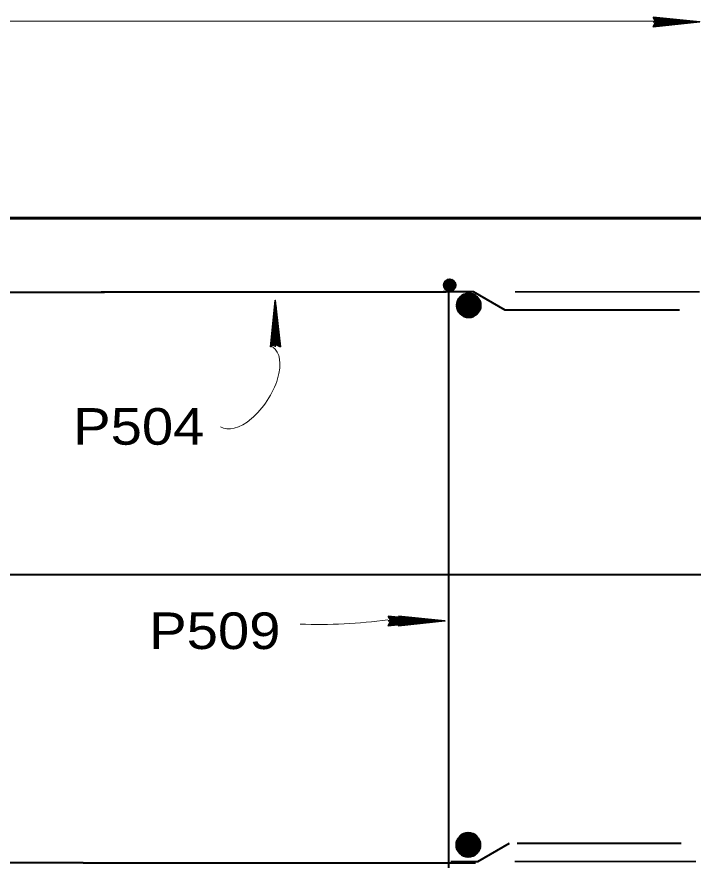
# Model space of a CAD drawing. Extents: x 3.64 to 6.84, y -0.8 to 1.19.
# Drawn here: x 4.3787 to 4.533, y 0.7206 to 0.9146 of the extents above; entities that cross this region are included whole.
import ezdxf

# ---------------------------------------------------------------- set-up
doc = ezdxf.new("R2010")
doc.units = 0
doc.header["$LTSCALE"] = 0.0033
doc.layers.add('1', color=7, linetype='Continuous', lineweight=40)

msp = doc.modelspace()

# ---------------------------------------------------------------- linework, layer by layer
at = {"layer": '1', "lineweight": 35}
for p, q in [((4.524, 0.9145), (4.531833, 0.913583)), ((4.524, 0.9145), (4.531833, 0.913583)), ((4.524, 0.914417), (4.531833, 0.913583)), ((4.524, 0.914333), (4.531833, 0.9135)), ((4.524, 0.914333), (4.531833, 0.913333)), ((4.52375, 0.9135), (4.534333, 0.9135)), ((4.523917, 0.912833), (4.53125, 0.913583)), ((4.524, 0.912667), (4.531333, 0.9135)), ((4.524, 0.912583), (4.531333, 0.913333)), ((4.524, 0.912417), (4.531333, 0.91325)), ((4.49225, 0.851917), (4.53425, 0.851917)), ((4.437583, 0.839417), (4.437583, 0.85)), ((4.437583, 0.839417), (4.437583, 0.85)), ((4.436583, 0.839667), (4.4375, 0.8475)), ((4.436583, 0.839667), (4.4375, 0.8475)), ((4.436583, 0.839667), (4.4375, 0.8475)), ((4.436583, 0.839667), (4.4375, 0.8475)), ((4.436667, 0.839667), (4.4375, 0.8475)), ((4.436667, 0.839667), (4.4375, 0.8475)), ((4.43675, 0.839667), (4.437583, 0.8475)), ((4.43675, 0.839667), (4.43775, 0.8475)), ((4.43675, 0.839667), (4.437583, 0.8475)), ((4.43675, 0.839667), (4.43775, 0.8475)), ((4.43825, 0.839583), (4.4375, 0.846917)), ((4.43825, 0.839583), (4.4375, 0.846917)), ((4.438417, 0.839667), (4.437583, 0.847)), ((4.438417, 0.839667), (4.437583, 0.847)), ((4.4385, 0.839667), (4.43775, 0.847)), ((4.4385, 0.839667), (4.43775, 0.847)), ((4.438667, 0.839667), (4.437833, 0.847)), ((4.438667, 0.839667), (4.437833, 0.847)), ((4.463333, 0.776917), (4.473917, 0.776917)), ((4.463333, 0.776917), (4.473917, 0.776917)), ((4.4635, 0.77625), (4.470833, 0.777)), ((4.4635, 0.77625), (4.470833, 0.777)), ((4.463583, 0.777917), (4.471417, 0.777)), ((4.463583, 0.777917), (4.471417, 0.777)), ((4.463583, 0.777917), (4.471417, 0.777)), ((4.463583, 0.777917), (4.471417, 0.777)), ((4.463583, 0.777833), (4.471417, 0.777)), ((4.463583, 0.777833), (4.471417, 0.777)), ((4.463583, 0.77775), (4.471417, 0.776917)), ((4.463583, 0.77775), (4.471417, 0.77675)), ((4.463583, 0.77775), (4.471417, 0.776917)), ((4.463583, 0.77775), (4.471417, 0.77675)), ((4.463583, 0.776083), (4.470917, 0.776917)), ((4.463583, 0.776083), (4.470917, 0.776917)), ((4.463583, 0.776), (4.470917, 0.77675)), ((4.463583, 0.776), (4.470917, 0.77675)), ((4.463583, 0.775833), (4.470917, 0.776667)), ((4.463583, 0.775833), (4.470917, 0.776667)), ((4.465667, 0.776917), (4.47625, 0.776917)), ((4.465667, 0.776917), (4.47625, 0.776917)), ((4.465833, 0.77625), (4.473167, 0.777)), ((4.465833, 0.77625), (4.473167, 0.777)), ((4.465917, 0.777917), (4.47375, 0.777)), ((4.465917, 0.777917), (4.47375, 0.777)), ((4.465917, 0.777917), (4.47375, 0.777)), ((4.465917, 0.777917), (4.47375, 0.777)), ((4.465917, 0.777833), (4.47375, 0.777)), ((4.465917, 0.777833), (4.47375, 0.777)), ((4.465917, 0.77775), (4.47375, 0.776917)), ((4.465917, 0.77775), (4.47375, 0.77675)), ((4.465917, 0.77775), (4.47375, 0.776917)), ((4.465917, 0.77775), (4.47375, 0.77675)), ((4.465917, 0.776083), (4.47325, 0.776917)), ((4.465917, 0.776083), (4.47325, 0.776917)), ((4.465917, 0.776), (4.47325, 0.77675)), ((4.465917, 0.776), (4.47325, 0.77675)), ((4.465917, 0.775833), (4.47325, 0.776667)), ((4.465917, 0.775833), (4.47325, 0.776667)), ((4.492167, 0.722083), (4.533417, 0.722083))]:
    msp.add_line(p, q, dxfattribs=at)
at = {"layer": '1', "lineweight": 13}
msp.add_line((4.117, 0.913667), (4.533, 0.913667), dxfattribs=at)
at = {"layer": '1', "lineweight": 60}
for p, q in [((4.157167, 0.86875), (4.492917, 0.86875)), ((4.399333, 0.86875), (4.53725, 0.86875)), ((4.479167, 0.84825), (4.479333, 0.850083)), ((4.479417, 0.850167), (4.479583, 0.84725)), ((4.479667, 0.850167), (4.479833, 0.84725)), ((4.479833, 0.850167), (4.480083, 0.84725)), ((4.48, 0.850167), (4.480167, 0.84725)), ((4.480167, 0.850167), (4.480417, 0.84725)), ((4.480417, 0.85025), (4.480583, 0.847333)), ((4.4805, 0.85025), (4.480667, 0.847333)), ((4.480667, 0.85025), (4.480833, 0.847333)), ((4.48075, 0.85025), (4.480917, 0.847333)), ((4.480917, 0.85025), (4.481167, 0.847333)), ((4.481167, 0.85025), (4.481417, 0.847333)), ((4.481417, 0.850333), (4.481583, 0.847417)), ((4.481583, 0.850333), (4.481833, 0.847417)), ((4.481833, 0.850333), (4.482, 0.847417)), ((4.482, 0.850333), (4.482167, 0.847417)), ((4.482167, 0.850333), (4.482333, 0.847417)), ((4.48225, 0.850417), (4.4825, 0.847417)), ((4.4825, 0.850417), (4.482667, 0.847417)), ((4.48275, 0.850417), (4.482917, 0.847417)), ((4.482917, 0.850417), (4.483167, 0.847417)), ((4.483083, 0.850417), (4.48325, 0.847417)), ((4.48325, 0.850417), (4.4835, 0.8475)), ((4.4835, 0.850417), (4.483667, 0.8475)), ((4.479167, 0.84825), (4.483917, 0.8475)), ((4.479083, 0.72525), (4.47925, 0.727083)), ((4.479333, 0.727167), (4.4795, 0.72425)), ((4.479583, 0.727167), (4.47975, 0.72425)), ((4.47975, 0.727167), (4.48, 0.72425)), ((4.479917, 0.727167), (4.480083, 0.72425)), ((4.480083, 0.727167), (4.480333, 0.72425)), ((4.480333, 0.72725), (4.4805, 0.724333)), ((4.480417, 0.72725), (4.480583, 0.724333)), ((4.480583, 0.72725), (4.48075, 0.724333)), ((4.480667, 0.72725), (4.480833, 0.724333)), ((4.480833, 0.72725), (4.481083, 0.724333)), ((4.481083, 0.72725), (4.481333, 0.724333)), ((4.481333, 0.727333), (4.4815, 0.724417)), ((4.4815, 0.727333), (4.48175, 0.724417)), ((4.48175, 0.727333), (4.481917, 0.724417)), ((4.481917, 0.727333), (4.482083, 0.724417)), ((4.482083, 0.727333), (4.48225, 0.724417)), ((4.482167, 0.727417), (4.482417, 0.724417)), ((4.482417, 0.727417), (4.482583, 0.724417)), ((4.482667, 0.727417), (4.482833, 0.724417)), ((4.482833, 0.727417), (4.483083, 0.724417)), ((4.483, 0.727417), (4.483167, 0.724417)), ((4.483167, 0.727417), (4.483417, 0.7245)), ((4.483417, 0.727417), (4.483583, 0.7245)), ((4.479083, 0.72525), (4.483833, 0.7245))]:
    msp.add_line(p, q, dxfattribs=at)
at = {"layer": '1'}
for p, q in [((4.476417, 0.85425), (4.476333, 0.85275)), ((4.476417, 0.85425), (4.476333, 0.85275)), ((4.476333, 0.85375), (4.478333, 0.853417)), ((4.476333, 0.85375), (4.478333, 0.853417)), ((4.476333, 0.853667), (4.478333, 0.85325)), ((4.476333, 0.853667), (4.478333, 0.85325)), ((4.4765, 0.85425), (4.476417, 0.85275)), ((4.476417, 0.85425), (4.478417, 0.853917)), ((4.4765, 0.85425), (4.476417, 0.85275)), ((4.476417, 0.85425), (4.478417, 0.853917)), ((4.476417, 0.854167), (4.478417, 0.853833)), ((4.476417, 0.854167), (4.478417, 0.853833)), ((4.476417, 0.854083), (4.478417, 0.853667)), ((4.476417, 0.854083), (4.478417, 0.853667)), ((4.476417, 0.854), (4.478417, 0.853583)), ((4.476417, 0.854), (4.478417, 0.853583)), ((4.476417, 0.853833), (4.478333, 0.8535)), ((4.476417, 0.853833), (4.478333, 0.8535)), ((4.4765, 0.854417), (4.478417, 0.854083)), ((4.4765, 0.854417), (4.478417, 0.854083)), ((4.476583, 0.85425), (4.4765, 0.85275)), ((4.476583, 0.85425), (4.4765, 0.85275)), ((4.476667, 0.85425), (4.476583, 0.85275)), ((4.476667, 0.85425), (4.476583, 0.85275)), ((4.47675, 0.85425), (4.476667, 0.85275)), ((4.47675, 0.85425), (4.476667, 0.85275)), ((4.476917, 0.85425), (4.476833, 0.85275)), ((4.476917, 0.85425), (4.476833, 0.85275)), ((4.477, 0.85425), (4.476917, 0.85275)), ((4.477, 0.85425), (4.476917, 0.85275)), ((4.477083, 0.85425), (4.477, 0.85275)), ((4.477083, 0.85425), (4.477, 0.85275)), ((4.477167, 0.85425), (4.477083, 0.85275)), ((4.477167, 0.85425), (4.477083, 0.85275)), ((4.47725, 0.85425), (4.477167, 0.85275)), ((4.47725, 0.85425), (4.477167, 0.85275)), ((4.477333, 0.85425), (4.47725, 0.85275)), ((4.477333, 0.85425), (4.47725, 0.85275)), ((4.477417, 0.85425), (4.477333, 0.85275)), ((4.477417, 0.85425), (4.477333, 0.85275)), ((4.477583, 0.854167), (4.477417, 0.852667)), ((4.477583, 0.854167), (4.477417, 0.852667)), ((4.47775, 0.854167), (4.477583, 0.852667)), ((4.47775, 0.854167), (4.477583, 0.852667)), ((4.477833, 0.854167), (4.47775, 0.852667)), ((4.477833, 0.854167), (4.47775, 0.852667)), ((4.477833, 0.854167), (4.47775, 0.852667)), ((4.477833, 0.854167), (4.47775, 0.852667)), ((4.477917, 0.854167), (4.477833, 0.852667)), ((4.477917, 0.854167), (4.477833, 0.852667)), ((4.478, 0.854167), (4.477917, 0.852667)), ((4.478, 0.854167), (4.477917, 0.852667)), ((4.478083, 0.854167), (4.478, 0.852667)), ((4.478083, 0.854167), (4.478, 0.852667)), ((4.478167, 0.854167), (4.478083, 0.852667)), ((4.478167, 0.854167), (4.478083, 0.852667)), ((4.47825, 0.854167), (4.478167, 0.852667)), ((4.47825, 0.854167), (4.478167, 0.852667)), ((4.478333, 0.854167), (4.47825, 0.852667)), ((4.478333, 0.854167), (4.47825, 0.852667)), ((4.4785, 0.854167), (4.478417, 0.852667)), ((4.4785, 0.854167), (4.478417, 0.852667)), ((4.397917, 0.851917), (4.4765, 0.851917)), ((4.476167, 0.852833), (4.478167, 0.8525)), ((4.476167, 0.852833), (4.478167, 0.8525)), ((4.47625, 0.853333), (4.47825, 0.852917)), ((4.47625, 0.853333), (4.47825, 0.852917)), ((4.47625, 0.853083), (4.47825, 0.85275)), ((4.47625, 0.853083), (4.47825, 0.85275)), ((4.47625, 0.853), (4.478167, 0.852667)), ((4.47625, 0.853), (4.478167, 0.852667)), ((4.47625, 0.852917), (4.478167, 0.852583)), ((4.47625, 0.852917), (4.478167, 0.852583)), ((4.476333, 0.853583), (4.47825, 0.853167)), ((4.476333, 0.853583), (4.47825, 0.853167)), ((4.476333, 0.8535), (4.47825, 0.853083)), ((4.476333, 0.8535), (4.47825, 0.853083)), ((4.477083, 0.851917), (4.477083, 0.720583)), ((4.477083, 0.851917), (4.477083, 0.720583)), ((4.48375, 0.850417), (4.479167, 0.84825)), ((4.479333, 0.850083), (4.480583, 0.85125)), ((4.483333, 0.85075), (4.4795, 0.850083)), ((4.483417, 0.850417), (4.4795, 0.84975)), ((4.483417, 0.85025), (4.4795, 0.8495)), ((4.4835, 0.85), (4.479583, 0.84925)), ((4.4835, 0.849833), (4.479583, 0.849083)), ((4.481417, 0.849917), (4.480083, 0.850917)), ((4.4835, 0.849583), (4.479667, 0.848833)), ((4.483583, 0.849417), (4.47975, 0.84875)), ((4.483583, 0.84925), (4.47975, 0.8485)), ((4.483667, 0.849), (4.479833, 0.84825)), ((4.483667, 0.848833), (4.479833, 0.848083)), ((4.48375, 0.848583), (4.479833, 0.847833)), ((4.483833, 0.848167), (4.479917, 0.847417)), ((4.483833, 0.848), (4.48, 0.84725)), ((4.479583, 0.84725), (4.483333, 0.846833)), ((4.483833, 0.84775), (4.48, 0.847083)), ((4.483917, 0.847667), (4.480083, 0.846917)), ((4.483917, 0.8475), (4.480083, 0.84675)), ((4.050917, 0.7875), (4.474833, 0.7875)), ((4.474833, 0.7875), (4.495917, 0.7875)), ((4.47925, 0.727083), (4.4805, 0.72825)), ((4.48325, 0.72775), (4.479417, 0.727083)), ((4.481333, 0.726917), (4.48, 0.727917)), ((4.483667, 0.727417), (4.479083, 0.72525)), ((4.483333, 0.727417), (4.479417, 0.72675)), ((4.483333, 0.72725), (4.479417, 0.7265)), ((4.483417, 0.727), (4.4795, 0.72625)), ((4.483417, 0.726833), (4.4795, 0.726083)), ((4.483417, 0.726583), (4.479583, 0.725833)), ((4.4835, 0.726417), (4.479667, 0.72575)), ((4.4835, 0.72625), (4.479667, 0.7255)), ((4.483583, 0.726), (4.47975, 0.72525)), ((4.483583, 0.725833), (4.47975, 0.725083)), ((4.483667, 0.725583), (4.47975, 0.724833)), ((4.530083, 0.726167), (4.49275, 0.726167)), ((4.4795, 0.72425), (4.48325, 0.723833)), ((4.48375, 0.725167), (4.479833, 0.724417)), ((4.48375, 0.725), (4.479917, 0.72425)), ((4.48375, 0.72475), (4.479917, 0.724083)), ((4.483833, 0.724667), (4.48, 0.723917)), ((4.483833, 0.7245), (4.48, 0.72375)), ((4.39375, 0.72175), (4.171167, 0.72175)), ((4.39375, 0.72175), (4.48325, 0.72175))]:
    msp.add_line(p, q, dxfattribs=at)
at = {"layer": '1', "lineweight": 35}
for points in [[(4.52375, 0.914583), (4.534333, 0.9135), (4.52375, 0.912333), (4.524333, 0.9135)], [(4.5245, 0.913583), (4.529167, 0.913667), (4.529167, 0.913583), (4.52825, 0.913583), (4.5245, 0.913667), (4.5275, 0.91375), (4.524333, 0.913833), (4.526583, 0.913917), (4.524333, 0.914), (4.527833, 0.91375), (4.5325, 0.913583), (4.531583, 0.913333), (4.532833, 0.913333), (4.5245, 0.913333), (4.526917, 0.913167), (4.524333, 0.913167), (4.529667, 0.913583), (4.524333, 0.912917)], [(4.4365, 0.839417), (4.437583, 0.85), (4.43875, 0.839417), (4.437583, 0.84)], [(4.4365, 0.839417), (4.437583, 0.85), (4.43875, 0.839417), (4.437583, 0.84)], [(4.4375, 0.840167), (4.437417, 0.844833), (4.4375, 0.844833), (4.4375, 0.843917), (4.437417, 0.840167), (4.437333, 0.843167), (4.43725, 0.84), (4.437167, 0.84225), (4.437083, 0.84), (4.437333, 0.8435), (4.4375, 0.848167), (4.43775, 0.84725), (4.43775, 0.8485), (4.43775, 0.840167), (4.437917, 0.842583), (4.437917, 0.84), (4.4375, 0.845333), (4.438167, 0.84)], [(4.4375, 0.840167), (4.437417, 0.844833), (4.4375, 0.844833), (4.4375, 0.843917), (4.437417, 0.840167), (4.437333, 0.843167), (4.43725, 0.84), (4.437167, 0.84225), (4.437083, 0.84), (4.437333, 0.8435), (4.4375, 0.848167), (4.43775, 0.84725), (4.43775, 0.8485), (4.43775, 0.840167), (4.437917, 0.842583), (4.437917, 0.84), (4.4375, 0.845333), (4.438167, 0.84)], [(4.463333, 0.778), (4.473917, 0.776917), (4.463333, 0.77575), (4.463917, 0.776917)], [(4.463333, 0.778), (4.473917, 0.776917), (4.463333, 0.77575), (4.463917, 0.776917)], [(4.465667, 0.778), (4.47625, 0.776917), (4.465667, 0.77575), (4.46625, 0.776917)], [(4.465667, 0.778), (4.47625, 0.776917), (4.465667, 0.77575), (4.46625, 0.776917)], [(4.464083, 0.777), (4.46875, 0.777083), (4.46875, 0.777), (4.467833, 0.777), (4.464083, 0.777083), (4.467083, 0.777167), (4.463917, 0.77725), (4.466167, 0.777333), (4.463917, 0.777417), (4.467417, 0.777167), (4.472083, 0.777), (4.471167, 0.77675), (4.472417, 0.77675), (4.464083, 0.77675), (4.4665, 0.776583), (4.463917, 0.776583), (4.46925, 0.777), (4.463917, 0.776333)], [(4.464083, 0.777), (4.46875, 0.777083), (4.46875, 0.777), (4.467833, 0.777), (4.464083, 0.777083), (4.467083, 0.777167), (4.463917, 0.77725), (4.466167, 0.777333), (4.463917, 0.777417), (4.467417, 0.777167), (4.472083, 0.777), (4.471167, 0.77675), (4.472417, 0.77675), (4.464083, 0.77675), (4.4665, 0.776583), (4.463917, 0.776583), (4.46925, 0.777), (4.463917, 0.776333)], [(4.466417, 0.777), (4.471083, 0.777083), (4.471083, 0.777), (4.470167, 0.777), (4.466417, 0.777083), (4.469417, 0.777167), (4.46625, 0.77725), (4.4685, 0.777333), (4.46625, 0.777417), (4.46975, 0.777167), (4.474417, 0.777), (4.4735, 0.77675), (4.47475, 0.77675), (4.466417, 0.77675), (4.468833, 0.776583), (4.46625, 0.776583), (4.471583, 0.777), (4.46625, 0.776333)], [(4.466417, 0.777), (4.471083, 0.777083), (4.471083, 0.777), (4.470167, 0.777), (4.466417, 0.777083), (4.469417, 0.777167), (4.46625, 0.77725), (4.4685, 0.777333), (4.46625, 0.777417), (4.46975, 0.777167), (4.474417, 0.777), (4.4735, 0.77675), (4.47475, 0.77675), (4.466417, 0.77675), (4.468833, 0.776583), (4.46625, 0.776583), (4.471583, 0.777), (4.46625, 0.776333)]]:
    msp.add_lwpolyline(points, close=True, dxfattribs=at)
for points in [[(4.5245, 0.913583), (4.524083, 0.914333), (4.524333, 0.914083), (4.5245, 0.91375), (4.52475, 0.913833), (4.524583, 0.914167), (4.524417, 0.913417), (4.52425, 0.912917), (4.524, 0.9125)], [(4.4375, 0.840167), (4.43675, 0.83975), (4.437, 0.84), (4.437333, 0.840167), (4.43725, 0.840417), (4.436917, 0.84025), (4.437667, 0.840083), (4.438167, 0.839917), (4.438583, 0.839667)], [(4.4375, 0.840167), (4.43675, 0.83975), (4.437, 0.84), (4.437333, 0.840167), (4.43725, 0.840417), (4.436917, 0.84025), (4.437667, 0.840083), (4.438167, 0.839917), (4.438583, 0.839667)], [(4.464083, 0.777), (4.463667, 0.77775), (4.463917, 0.7775), (4.464083, 0.777167), (4.464333, 0.77725), (4.464167, 0.777583), (4.464, 0.776833), (4.463833, 0.776333), (4.463583, 0.775917)], [(4.464083, 0.777), (4.463667, 0.77775), (4.463917, 0.7775), (4.464083, 0.777167), (4.464333, 0.77725), (4.464167, 0.777583), (4.464, 0.776833), (4.463833, 0.776333), (4.463583, 0.775917)], [(4.466417, 0.777), (4.466, 0.77775), (4.46625, 0.7775), (4.466417, 0.777167), (4.466667, 0.77725), (4.4665, 0.777583), (4.466333, 0.776833), (4.466167, 0.776333), (4.465917, 0.775917)], [(4.466417, 0.777), (4.466, 0.77775), (4.46625, 0.7775), (4.466417, 0.777167), (4.466667, 0.77725), (4.4665, 0.777583), (4.466333, 0.776833), (4.466167, 0.776333), (4.465917, 0.775917)]]:
    msp.add_lwpolyline(points, dxfattribs=at)
at = {"layer": '1'}
for points in [[(4.476, 0.853417), (4.478583, 0.85375), (4.47625, 0.85425), (4.478583, 0.853167), (4.476167, 0.85275), (4.478167, 0.852417), (4.478167, 0.8545), (4.47725, 0.852167), (4.4775, 0.85475), (4.4765, 0.852417), (4.476833, 0.85475), (4.477667, 0.852167), (4.476083, 0.853917), (4.4785, 0.854083), (4.476833, 0.85225), (4.477917, 0.854667), (4.47625, 0.85425), (4.476167, 0.85275), (4.47725, 0.852167), (4.478167, 0.852417), (4.478583, 0.853167), (4.4785, 0.854083), (4.477917, 0.854667), (4.47725, 0.853583), (4.478417, 0.852667), (4.4765, 0.852417), (4.47725, 0.853583), (4.476167, 0.854083), (4.477167, 0.85475), (4.47725, 0.853667), (4.478083, 0.852417), (4.476083, 0.853667), (4.477417, 0.854), (4.478167, 0.8545)], [(4.476167, 0.85275), (4.47725, 0.852167), (4.478167, 0.852417), (4.478583, 0.853167), (4.4785, 0.854083), (4.477917, 0.854667), (4.47725, 0.853583), (4.478417, 0.852667), (4.4765, 0.852417), (4.47725, 0.853583), (4.476167, 0.854083), (4.477167, 0.85475), (4.47725, 0.853667), (4.478083, 0.852417), (4.476083, 0.853667), (4.477417, 0.854), (4.478167, 0.8545)], [(4.478583, 0.85375), (4.47625, 0.85425), (4.478583, 0.853167)], [(4.121083, 0.847667), (4.161583, 0.847667), (4.168833, 0.851833), (4.398667, 0.851833)], [(4.52975, 0.84775), (4.49, 0.84775), (4.48275, 0.851917), (4.475833, 0.851917)], [(4.483917, 0.8475), (4.481833, 0.84625), (4.480083, 0.84675), (4.479167, 0.84825)], [(4.39625, 0.7875), (4.474833, 0.7875), (4.598833, 0.7875)], [(4.490917, 0.726167), (4.483667, 0.722), (4.477583, 0.722)], [(4.483833, 0.7245), (4.48175, 0.72325), (4.48, 0.72375), (4.479083, 0.72525)]]:
    msp.add_lwpolyline(points, dxfattribs=at)
msp.add_lwpolyline([(4.476167, 0.85275), (4.478167, 0.852417), (4.478167, 0.8545), (4.47725, 0.852167), (4.4775, 0.85475), (4.4765, 0.852417), (4.476833, 0.85475), (4.477667, 0.852167), (4.476083, 0.853917), (4.4785, 0.854083), (4.476833, 0.85225), (4.477917, 0.854667), (4.47625, 0.85425)], close=True, dxfattribs=at)
at = {"layer": '1', "lineweight": 60}
for points in [[(4.484333, 0.84875), (4.479167, 0.849417), (4.48375, 0.850417)], [(4.480083, 0.84675), (4.480083, 0.850917), (4.48175, 0.84625), (4.48125, 0.851417), (4.483333, 0.846833), (4.482583, 0.851333), (4.481, 0.846333), (4.484167, 0.849667), (4.479333, 0.850083), (4.482583, 0.846417), (4.480583, 0.85125), (4.48375, 0.850417), (4.483917, 0.8475)], [(4.480583, 0.85125), (4.481833, 0.849083), (4.479583, 0.84725)], [(4.483333, 0.846833), (4.481833, 0.849083), (4.484, 0.85), (4.482, 0.851417), (4.481833, 0.849167), (4.480167, 0.846833), (4.484167, 0.849167), (4.481417, 0.849917)], [(4.48, 0.72375), (4.48, 0.727917), (4.481667, 0.72325), (4.481167, 0.728417), (4.48325, 0.723833), (4.4825, 0.728333), (4.480917, 0.723333), (4.484083, 0.726667), (4.47925, 0.727083), (4.4825, 0.723417), (4.4805, 0.72825), (4.483667, 0.727417), (4.483833, 0.7245)], [(4.4805, 0.72825), (4.48175, 0.726083), (4.4795, 0.72425)], [(4.48325, 0.723833), (4.48175, 0.726083), (4.483917, 0.727), (4.481917, 0.728417), (4.48175, 0.726167), (4.480083, 0.723833), (4.484083, 0.726167), (4.481333, 0.726917)], [(4.48425, 0.72575), (4.479083, 0.726417), (4.483667, 0.727417)]]:
    msp.add_lwpolyline(points, dxfattribs=at)
at = {"layer": '1'}
msp.add_circle((4.477333, 0.853467), 0.00132, dxfattribs=at)
at = {"layer": '1', "lineweight": 60}
for centre in [(4.481667, 0.84885), (4.481583, 0.72585)]:
    msp.add_circle(centre, 0.00264, dxfattribs=at)
at = {"layer": '1', "lineweight": 13}
msp.add_arc((4.447257, 0.896531), 0.120431, 268.09338, 277.63143, dxfattribs=at)
msp.add_arc((4.447257, 0.896531), 0.120431, 268.09338, 277.63143, dxfattribs=at)
msp.add_ellipse((4.431042, 0.83025), major_axis=(-0.005958, -0.009083), ratio=0.519389, start_param=6.2831853, end_param=9.424778, dxfattribs=at)

# ---------------------------------------------------------------- texts
at = {"layer": '1', "width": 1.15}
for s, p in [('P504', (4.3915, 0.817083)), ('P509', (4.408833, 0.7705)), ('P509', (4.408833, 0.7705))]:
    msp.add_text(s, height=0.008334, dxfattribs=at).set_placement(p)

doc.saveas('drawing.dxf')
